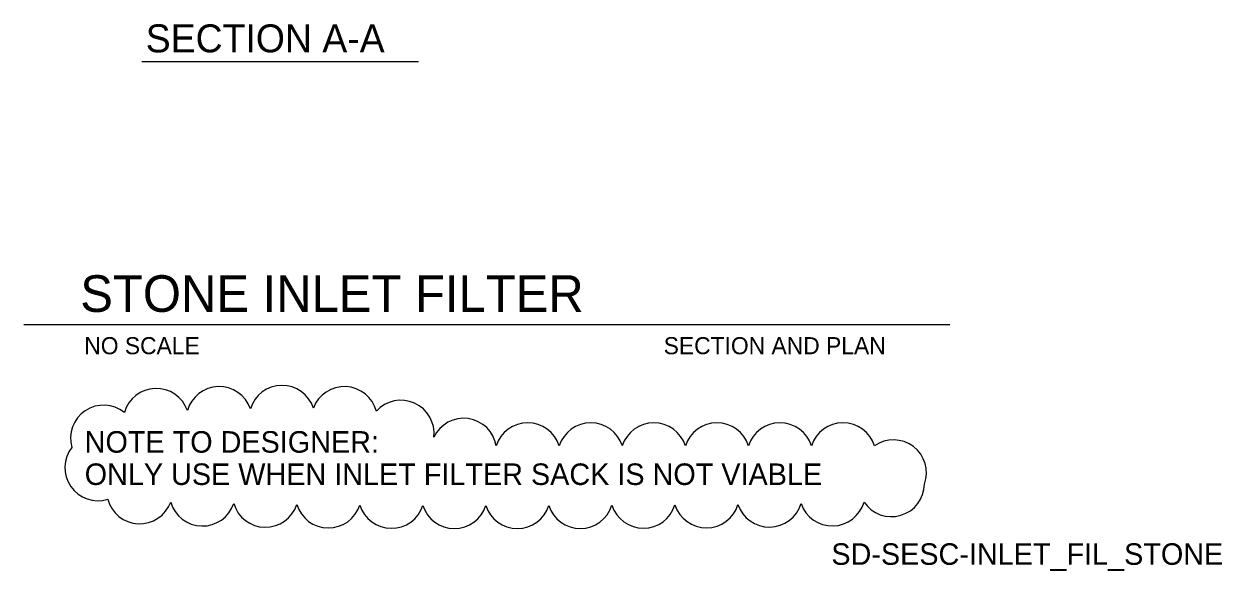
# Model space of a CAD drawing. Extents: x 9962.8 to 10024.8, y 9905.2 to 10002.8.
# Drawn here: x 9965.1 to 10023.2, y 9905.2 to 9931.7 of the extents above; entities that cross this region are included whole.
import ezdxf

# ---------------------------------------------------------------- set-up
doc = ezdxf.new("R2010")
doc.units = 0
for name, color, linetype in [('G-ANNO-TEXT', 7, 'Continuous'), ('G-ANNO-TTXT', 7, 'Continuous'), ('G-DETL-OTLN', 7, 'Continuous')]:
    doc.layers.add(name, color=color, linetype=linetype)

msp = doc.modelspace()

# ---------------------------------------------------------------- linework, layer by layer
at = {"layer": 'G-ANNO-TEXT'}
for p, q in [((9970.846, 9929.912), (9984.257, 9929.912)), ((9965.123, 9917.149), (10010.022, 9917.149))]:
    msp.add_line(p, q, dxfattribs=at)
at = {"layer": 'G-DETL-OTLN'}
for centre, radius, start, end in [((9971.534, 9912.453), 1.603, 19.1772, 164.1772), ((9974.589, 9912.542), 1.603, 19.15948, 164.15948), ((9977.636, 9912.601), 1.603, 18.0387, 163.0387), ((9980.663, 9912.542), 1.603, 14.71915, 159.71915), ((9968.987, 9911.642), 1.603, 51.15751, 196.15751), ((9983.408, 9911.881), 1.602, 353.22189, 138.22189), ((9986.447, 9911.004), 1.603, 9.58351, 154.58351), ((9989.555, 9910.789), 1.603, 17.5, 162.5), ((9992.612, 9910.789), 1.603, 17.5, 162.5), ((9995.669, 9910.789), 1.603, 17.5, 162.5), ((9998.726, 9910.789), 1.603, 17.5, 162.5), ((10001.782, 9910.789), 1.603, 17.5, 162.5), ((10004.839, 9910.789), 1.603, 17.5, 162.5), ((10007.289, 9909.961), 1.601, 340.11999, 125.11999), ((9968.713, 9910.213), 1.602, 142.15912, 287.15912), ((10007.19, 9909.443), 1.604, 214.05152, 359.05152), ((9970.735, 9909.093), 1.603, 194.86221, 339.86221), ((9973.779, 9908.987), 1.603, 196.13752, 341.13752), ((10004.322, 9908.99), 1.603, 198.89215, 343.89215), ((9976.831, 9908.929), 1.603, 196.68811, 341.68811), ((9979.884, 9908.894), 1.603, 197.01611, 342.01611), ((9982.939, 9908.874), 1.603, 197.24029, 342.24029), ((9985.995, 9908.865), 1.603, 197.40603, 342.40603), ((9989.05, 9908.863), 1.603, 197.52747, 342.52747), ((9992.106, 9908.868), 1.603, 197.63409, 342.63409), ((9995.162, 9908.878), 1.603, 197.77412, 342.77412), ((9998.217, 9908.898), 1.603, 197.97189, 342.97189), ((10001.271, 9908.932), 1.603, 198.28311, 343.28311)]:
    msp.add_arc(centre, radius, start, end, dxfattribs=at)

# ---------------------------------------------------------------- texts
at = {"layer": 'G-ANNO-TEXT'}
for s, height, p in [('STONE INLET FILTER', 1.776, (9967.854, 9917.767)), ('NO SCALE', 0.828, (9968.048, 9915.714)), ('SECTION AND PLAN', 0.828, (9996.146, 9915.714)), ('NOTE TO DESIGNER:', 1.044, (9968.067, 9910.939)), ('ONLY USE WHEN INLET FILTER SACK IS NOT VIABLE', 1.044, (9968.067, 9909.373)), ('SD-SESC-INLET_FIL_STONE', 1.044, (10004.277, 9905.501))]:
    msp.add_text(s, height=height, dxfattribs=at).set_placement(p)
at = {"layer": 'G-ANNO-TTXT'}
msp.add_text('SECTION A-A', height=1.356, dxfattribs=at).set_placement((9971.028, 9930.353))

doc.saveas('drawing.dxf')
